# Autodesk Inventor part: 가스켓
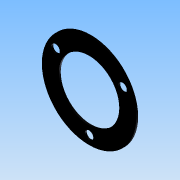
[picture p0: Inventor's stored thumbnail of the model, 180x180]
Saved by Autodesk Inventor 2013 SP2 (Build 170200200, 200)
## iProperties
Created: 2025-10
Part Number: 가스켓
Material: Generic
Document SubType Name: Modeling
Designer: 601
Density: 1 g/cm^3
Author: 601
변환 표준: STEP AP214IS
전처리기: Build: 200, Release: 2013 SP2 Update 6 - Date: Thu 07/17/2014
전송 단위: 밀리미터
불확실성: 0.01
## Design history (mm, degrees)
node "가스켓1"
node "솔리드1"
node "기준1"
